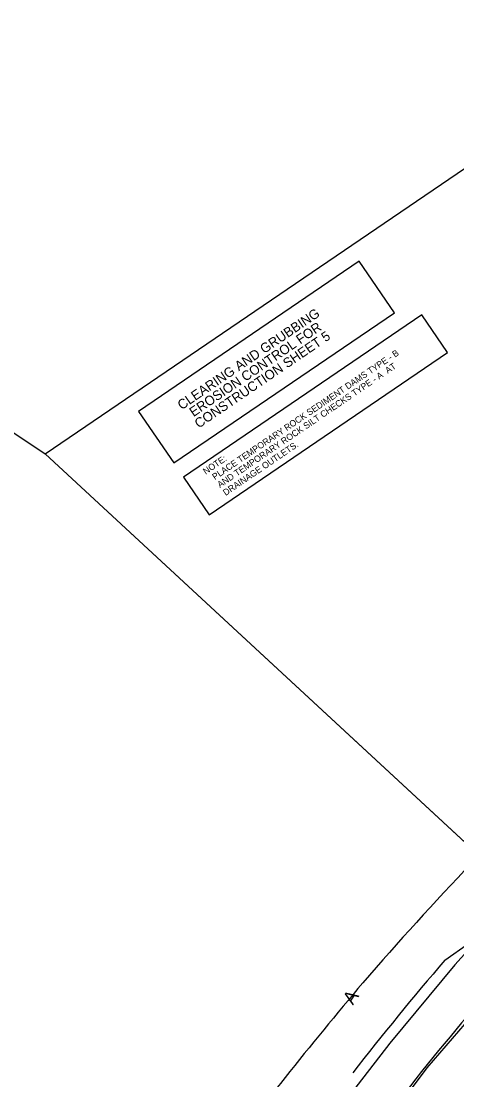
# Model space of a CAD drawing. Extents: x 2357856 to 2382083, y 331121 to 347536.
# Drawn here: x 2380227 to 2380554, y 332460 to 333255 of the extents above; entities that cross this region are included whole.
import ezdxf

# ---------------------------------------------------------------- set-up
doc = ezdxf.new("R2010")
doc.units = 0
for name, color, linetype in [('Cogo_Default_Point_CELL', 7, 'Continuous'), ('Coir Fiber Wattle Both CELL', 7, 'Continuous'), ('Default', 7, 'Continuous'), ('P_NCDOT_Horizontal_Alignment_Tick_Small', 7, 'Continuous'), ('P_RDY_North_Arrow_for_Plan_Sheets_CELL', 7, 'Continuous'), ('Sheet Data Field CELL', 7, 'Continuous'), ('Sheet_Named_Boundary', 7, 'Continuous')]:
    doc.layers.add(name, color=color, linetype=linetype)

# ---------------------------------------------------------------- blocks, each defined once
blk = doc.blocks.new('CGNT2')
at = {"layer": 'Cogo_Default_Point_CELL'}
blk.add_lwpolyline([(-0.09013, 0.01437), (-0.09013, -0.01433), (0.09013, -0.01433), (0.09013, 0.01437)], close=True, dxfattribs=at)
for s, p in [('NOTE:', (-0.07783, 0.0077)), ('     PLACE TEMPORARY ROCK SEDIMENT DAMS TYPE - B', (-0.08242, 0.00163)), ('     AND TEMPORARY ROCK SILT CHECKS TYPE - A  AT', (-0.0826, -0.0042)), ('     DRAINAGE OUTLETS.', (-0.08246, -0.0103))]:
    blk.add_text(s, height=0.004, dxfattribs=at).set_placement(p)

msp = doc.modelspace()

# ---------------------------------------------------------------- linework, layer by layer
at = {"layer": 'Coir Fiber Wattle Both CELL'}
msp.add_line((2380545.07, 332549.52), (2380562.74, 332562.2), dxfattribs=at)
for radius, start, end in [(2085, 139.25096, 142.25411), (2045, 139.26365, 142.29397)]:
    msp.add_arc((2382124.62, 331188.54), radius, start, end, dxfattribs=at)
at = {"layer": 'Default'}
for points in [[(2380245.38, 332929.65), (2381505.45, 333788.59), (2382082.78, 332941.65), (2381016.75, 332214.98)], [(2379358.12, 331688.32), (2380202.89, 332957.93), (2380245.38, 332929.65), (2380969.09, 332259.14), (2380211.47, 331120.52)]]:
    msp.add_lwpolyline(points, close=True, dxfattribs=at)
at = {"layer": 'P_RDY_North_Arrow_for_Plan_Sheets_CELL'}
msp.add_lwpolyline([(2380480.86, 333074.41), (2380315.37, 332961.6), (2380341.74, 332922.92), (2380507.22, 333035.74)], close=True, dxfattribs=at)
at = {"layer": 'Sheet Data Field CELL'}
for points in [[(2380609.99, 332609.75), (2380552.58, 332545.97), (2380503.7, 332487.22), (2380454.61, 332423.45)], [(2380435.05, 332338.96), (2380531.76, 332468.65), (2380565, 332507.19)]]:
    msp.add_lwpolyline(points, dxfattribs=at)
at = {"layer": 'Sheet_Named_Boundary'}
for centre, radius, start, end in [((2382262.22, 330998.25), 2349, 136.26014, 139.21866), ((2382983.23, 330423.97), 3270.26, 139.85098, 143.07409)]:
    msp.add_arc(centre, radius, start, end, dxfattribs=at)

# ---------------------------------------------------------------- block references
at = {"layer": 'Cogo_Default_Point_CELL', "xscale": 1199.9999999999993, "yscale": 1200, "rotation": 34.28489967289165}
msp.add_blockref('CGNT2', (2380448.05, 332959), dxfattribs=at)

# ---------------------------------------------------------------- texts
at = {"layer": 'P_NCDOT_Horizontal_Alignment_Tick_Small'}
msp.add_text('A', height=10, rotation=56.36098, dxfattribs=at).set_placement((2380476.08, 332515.41))
at = {"layer": 'P_RDY_North_Arrow_for_Plan_Sheets_CELL'}
for s, p in [('CLEARING AND GRUBBING', (2380347.64, 332962.47)), ('EROSION CONTROL FOR', (2380356.54, 332957.26)), ('CONSTRUCTION SHEET 5', (2380360.43, 332948.64))]:
    msp.add_text(s, height=7.2, rotation=34.2849, dxfattribs=at).set_placement(p)

doc.saveas('drawing.dxf')
